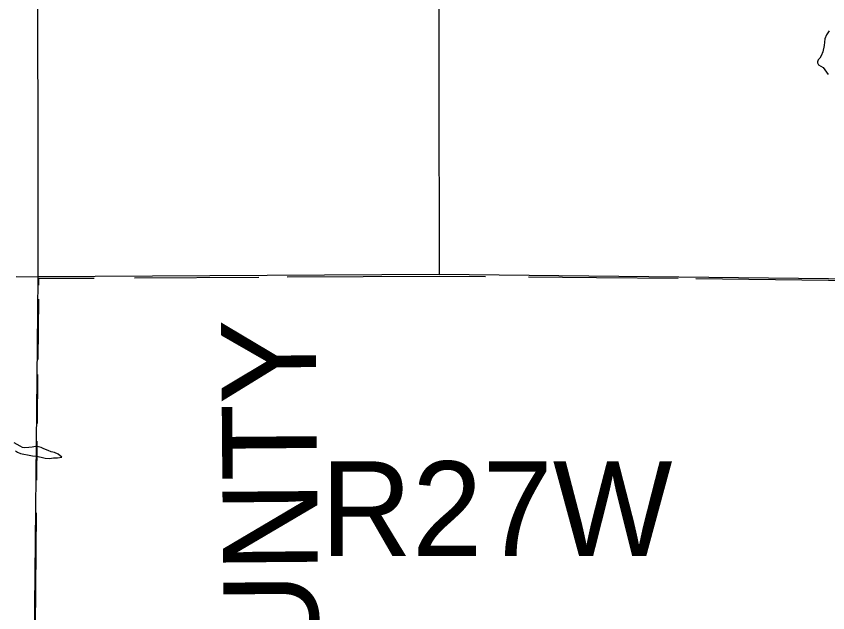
# Model space of a CAD drawing. Extents: x 77230 to 630905, y 790554 to 1662844.
# Drawn here: x 333032 to 343888, y 1564948 to 1572930 of the extents above; entities that cross this region are included whole.
import ezdxf

# ---------------------------------------------------------------- set-up
doc = ezdxf.new("R2010")
doc.units = 0
for name, color, linetype in [('Level 16', 7, 'Continuous'), ('Level 17', 7, 'Continuous'), ('Level 18', 7, 'Continuous'), ('Level 28', 7, 'Continuous'), ('Level 43', 7, 'Continuous')]:
    doc.layers.add(name, color=color, linetype=linetype)

msp = doc.modelspace()

# ---------------------------------------------------------------- linework, layer by layer
at = {"layer": 'Level 16'}
for points in [[(333468, 1579871), (333317, 1574735), (333323, 1569445)], [(338682, 1574722), (338690, 1569474)], [(333032, 1569447), (333032, 1569447)], [(333032, 1569447), (333323, 1569445)]]:
    msp.add_lwpolyline(points, dxfattribs=at)
at = {"layer": 'Level 17'}
for points in [[(343905, 1572737), (343872, 1572683), (343847, 1572626), (343839, 1572540), (343822, 1572452), (343801, 1572399), (343780, 1572371), (343762, 1572346), (343751, 1572318), (343750, 1572305), (343766, 1572280), (343797, 1572264), (343825, 1572242), (343847, 1572214), (343892, 1572151)], [(343905, 1572737), (343872, 1572683), (343847, 1572626), (343839, 1572540), (343822, 1572452), (343801, 1572399), (343780, 1572371), (343762, 1572346), (343751, 1572318), (343750, 1572305), (343766, 1572280), (343797, 1572264), (343825, 1572242), (343847, 1572214), (343892, 1572151)], [(333023, 1567115), (333051, 1567098), (333088, 1567080), (333132, 1567069), (333184, 1567061), (333250, 1567048), (333302, 1567041), (333368, 1567028), (333418, 1567017), (333476, 1567012), (333532, 1567019), (333584, 1567019), (333644, 1567030), (333593, 1567071), (333543, 1567091), (333499, 1567100), (333461, 1567120), (333400, 1567143), (333364, 1567158), (333330, 1567170), (333290, 1567173), (333244, 1567164), (333202, 1567160), (333148, 1567155), (333116, 1567161), (333086, 1567176), (333044, 1567200), (333005, 1567223)]]:
    msp.add_lwpolyline(points, dxfattribs=at)
at = {"layer": 'Level 18'}
for points in [[(343905, 1572737), (343872, 1572683), (343847, 1572626), (343839, 1572540), (343822, 1572452), (343801, 1572399), (343780, 1572371), (343762, 1572346), (343751, 1572318), (343750, 1572305), (343766, 1572280), (343797, 1572264), (343825, 1572242), (343847, 1572214), (343892, 1572151)], [(343905, 1572737), (343872, 1572683), (343847, 1572626), (343839, 1572540), (343822, 1572452), (343801, 1572399), (343780, 1572371), (343762, 1572346), (343751, 1572318), (343750, 1572305), (343766, 1572280), (343797, 1572264), (343825, 1572242), (343847, 1572214), (343892, 1572151)], [(349212, 1569314), (343898, 1569418), (338690, 1569474), (333323, 1569445)], [(333323, 1569445), (333318, 1568972)], [(333317, 1568972), (333269, 1564152), (333313, 1558859), (333315, 1557321)]]:
    msp.add_lwpolyline(points, dxfattribs=at)
at = {"layer": 'Level 43'}
for points in [[(333330, 1569423), (333329, 1569332)], [(333330, 1569423), (334074, 1569427)], [(334616, 1569430), (336279, 1569439)], [(336656, 1569441), (338688, 1569452), (339308, 1569447)], [(339883, 1569443), (340795, 1569436), (341886, 1569423)], [(342123, 1569420), (343897, 1569400), (347233, 1569333)], [(333328, 1569145), (333320, 1568336)], [(333318, 1568134), (333312, 1567479)], [(333309, 1567245), (333304, 1566723)], [(333300, 1566286), (333281, 1564256)]]:
    msp.add_lwpolyline(points, dxfattribs=at)

# ---------------------------------------------------------------- texts
at = {"layer": 'Level 28'}
msp.add_text('COUNTY', height=1267.2, rotation=90.4711, dxfattribs=at).set_placement((337098, 1561726))
msp.add_text('R27W', height=1267.2, dxfattribs=at).set_placement((337102, 1565707))

doc.saveas('drawing.dxf')
